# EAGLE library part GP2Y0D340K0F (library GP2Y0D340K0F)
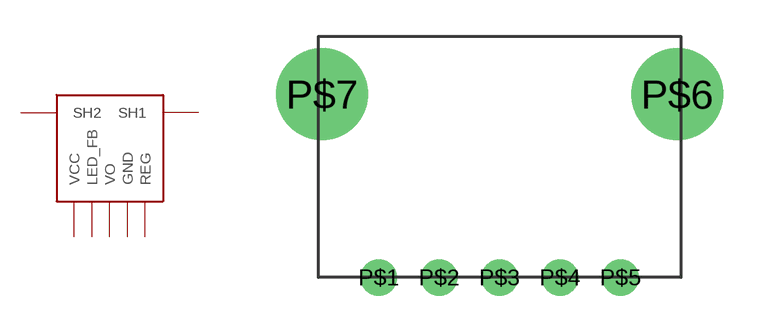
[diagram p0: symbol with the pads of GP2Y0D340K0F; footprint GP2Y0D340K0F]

Designator prefix -

## GP2Y0D340K0F  [GP2Y0D340K0F]
P$1  VCC
P$2  LED_FB
P$3  VO
P$4  GND
P$5  REG
P$6  SH1
P$7  SH2

## Footprint GP2Y0D340K0F (pad centres in mm)
drill 1 round: P$1 -4.96,-5.08; P$2 -2.46,-5.08; P$3 0.04,-5.08; P$4 2.54,-5.08; P$5 5.04,-5.08
drill 2.8 round: P$6 7.39,2.52; P$7 -7.31,2.52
